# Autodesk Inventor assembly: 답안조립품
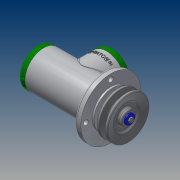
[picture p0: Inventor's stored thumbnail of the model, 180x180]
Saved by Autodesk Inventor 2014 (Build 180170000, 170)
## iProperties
Created: 2016-08
Part Number: 답안조립품
Document SubType Name: Assembly
Designer: 406-05
Author: 406-05
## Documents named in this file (25)
- C:\Users\406-05\Desktop\460807V1026\답안조립품.iam
- C:\Users\406-05\Desktop\460807V1026\본체.ipt
- C:\Users\406-05\Desktop\460807V1026\편심축.ipt
- C:\Users\406-05\Desktop\460807V1026\링크.ipt
- C:\Users\406-05\Desktop\460807V1026\클래스터 핀 6 x 24.ipt
- C:\Users\406-05\Desktop\460807V1026\슬라이더.ipt
- C:\Users\406-05\Desktop\460807V1026\베어링 15 x 35 x 11.ipt
- C:\Users\406-05\Desktop\460807V1026\부시1.ipt
- C:\Users\406-05\Desktop\460807V1026\멈춤링 35x1.6.ipt
- C:\Users\406-05\Desktop\460807V1026\부시2.ipt
- C:\Users\406-05\Desktop\460807V1026\와셔 10x21.ipt
- C:\Users\406-05\Desktop\460807V1026\너트 M10.ipt
- C:\Users\406-05\Desktop\460807V1026\멈춤링 15 x 1.ipt
- C:\Users\406-05\Desktop\460807V1026\키 4 x 4 x 18.ipt
- C:\Users\406-05\Desktop\460807V1026\분할핀 1.6 x 12.ipt
- C:\Users\406-05\Desktop\460807V1026\오일 실 15 25 7.ipt
- C:\Users\406-05\Desktop\460807V1026\V-벨트풀리.ipt
- C:\Users\406-05\Desktop\460807V1026\와셔 4x16.ipt
- C:\Users\406-05\Desktop\460807V1026\볼트 M4 x 10.ipt
- C:\Users\406-05\Desktop\460807V1026\사이드 커버.ipt
- 사이드 커버.ipt
- C:\Users\406-05\Desktop\460807V1026\탑 커버.ipt
- 탑 커버.ipt
- C:\Users\406-05\Desktop\460807V1026\볼트 M4 x 12.ipt
- C:\Users\406-05\Desktop\460807V1026\탑 부시.ipt
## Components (6 placed, 3 different names)
1. V-벨트풀리:1
2. ISO 4017 M4 x 10:1 — 각도:4
3. ISO 4762 M4 x 12:1 — 각도:6
4. ISO 4762 M4 x 12:2
5. ISO 4762 M4 x 12:3
6. ISO 4762 M4 x 12:4
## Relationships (2: Angle 2)
- 각도:4 [Angle]: ISO 4017 M4 x 10:1
- 각도:6 [Angle]: ISO 4762 M4 x 12:1
